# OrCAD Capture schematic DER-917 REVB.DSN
size Custom
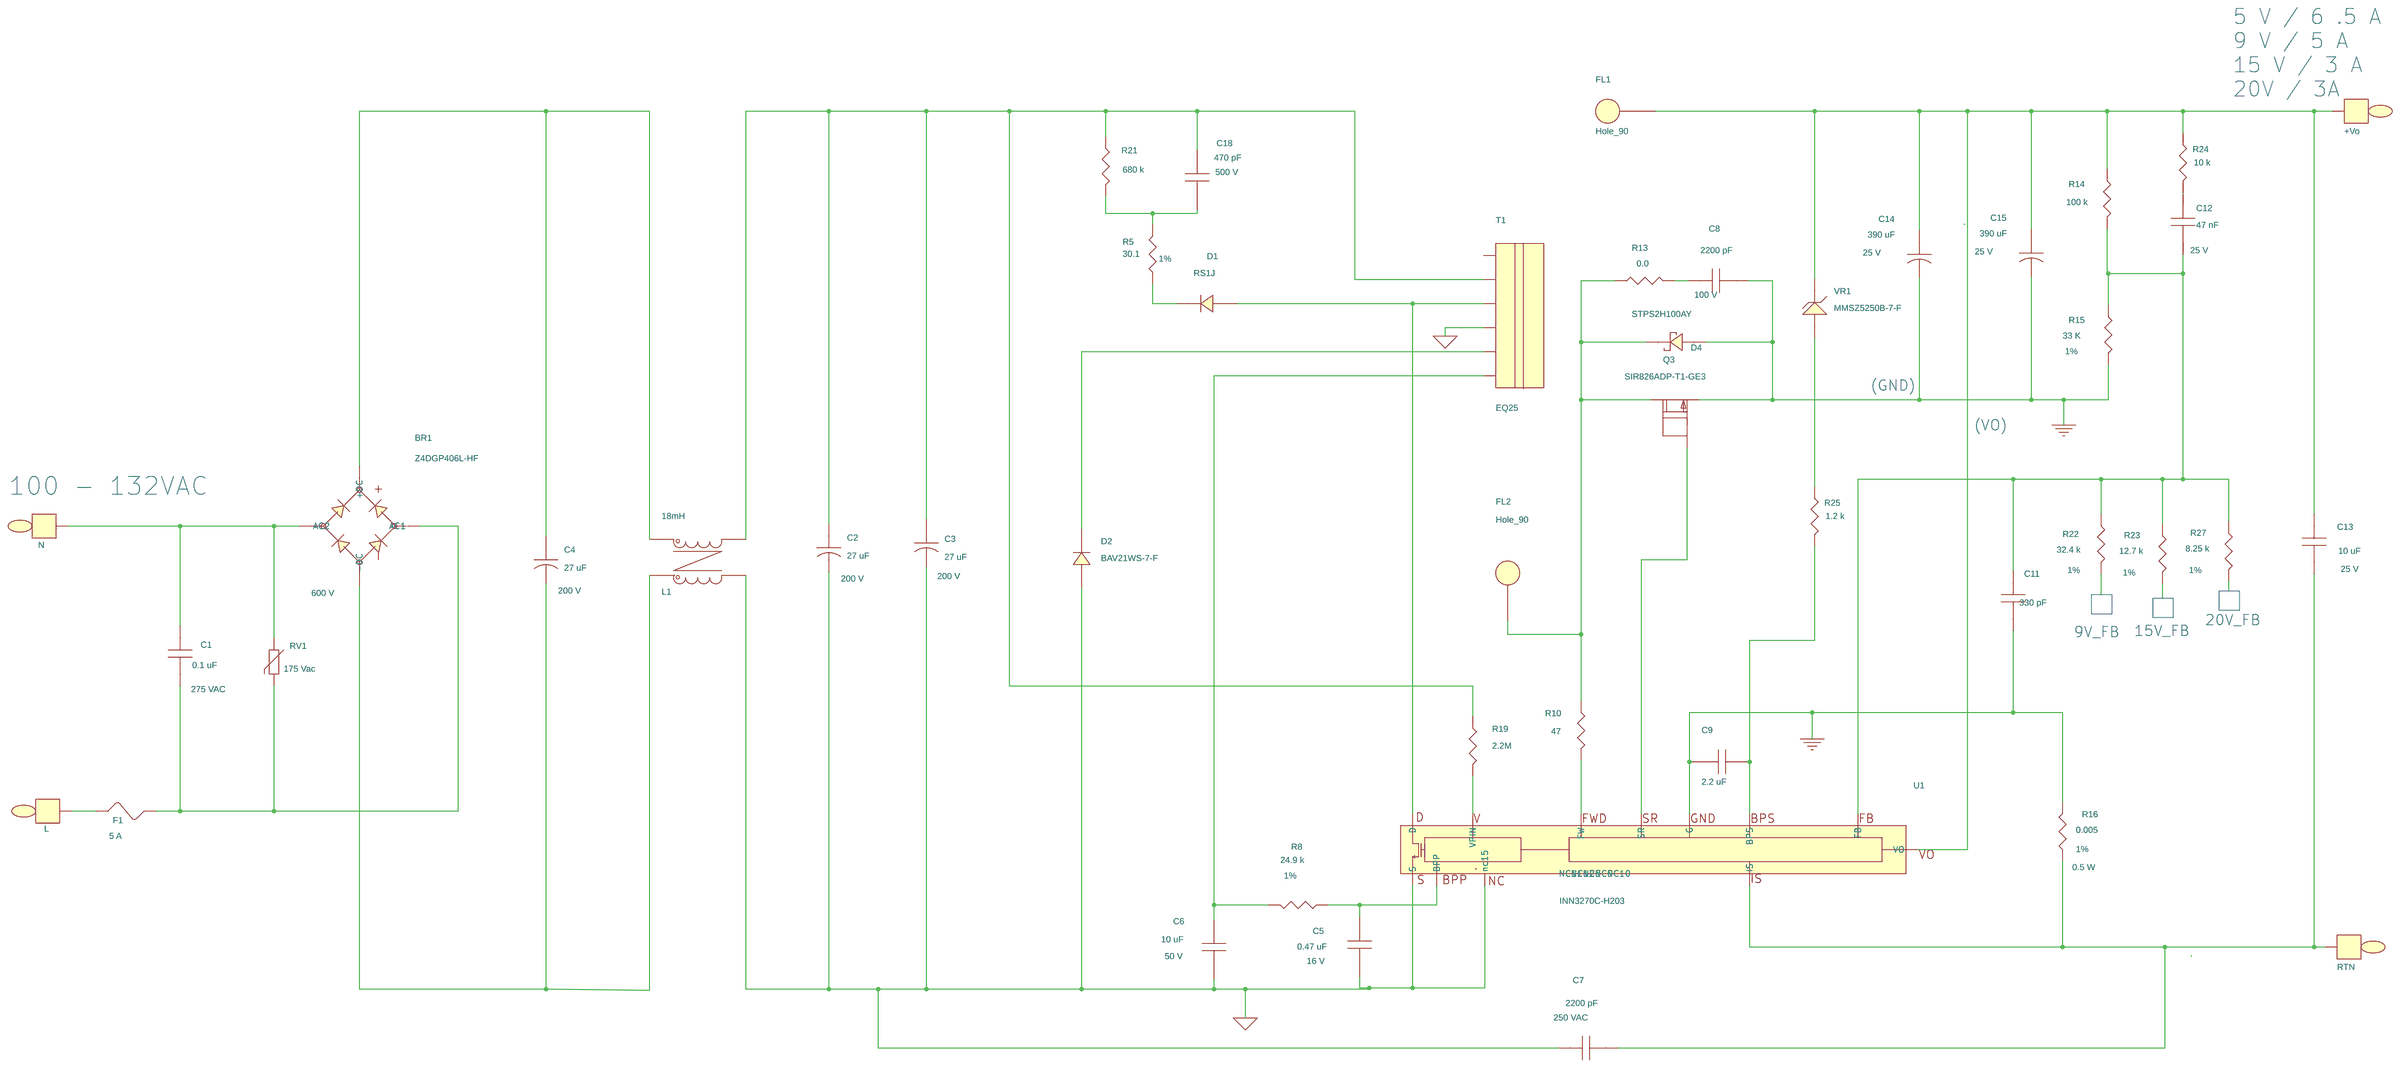
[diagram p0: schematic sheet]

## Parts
BR1  Z4DGP406L-HF  [pi_sm_d_z4d]
C1  0.1 uF  [pinpxcaprad5x13x11p1mm040]
C2  27 uF  [pipolcapcyld400ls200040]
C3  27 uF  [pipolcapcyld400ls200040]
C4  27 uF  [pipolcapcyld400ls200040]
C5  0.47 uF  [pismc0603]
C6  10 uF  [pismc1206]
C7  2200 pF  [pinpcaprad9p0D10p0LS030]
C8  2200 pF  [pismc0603]
C9  2.2 uF  [pismc0603]
C11  330 pF  [pismc0603]
C12  47 nF  [pismc0603]
C13  10 uF  [pismc1206]
C14  390 uF  [pipolcapcyld400ls200040]
C15  390 uF  [pipolcapcyld400ls200040]
C18  470 pF  [pismc0805]
D1  RS1J  [pismdsma]
D2  BAV21WS-7-F  [pismsod323]
D4  STPS2H100AY  [pismdsma]
F1  5 A  [pi_rst_microfuse]
FL1  Hole_90  [pi_hole_70mil]
FL2  Hole_90  [pi_hole_70mil]
L1  18mH  [pi_CMC_18mH_Sumida]
Q3  SIR826ADP-T1-GE3  [pismpqfn5x6b]
R5  30.1  [pismr0805]
R8  24.9 k  [pismr0603]
R10  47  [pismr0603]
R13  0.0  [pismr1206]
R14  100 k  [pismr0603]
R15  33 K  [pismr0603]
R16  0.005  [pismr0805]
R19  2.2M  [pismr1206]
R21  680 k  [pismr0805]
R22  32.4 k  [pismr0603]
R23  12.7 k  [pismr0603]
R24  10 k  [pismr0603]
R25  1.2 k  [pismr0603]
R27  8.25 k  [pismr0603]
RV1  175 Vac  [pi_disc_335x240ls200d040]
T1  EQ25  [pi_bobbin_eq-25_6p]
TP1  N  [pitpkeystone100x100]
TP2  L  [pitpkeystone100x100]
TP10  RTN  [pitpkeystone100x100]
TP11  +Vo  [pitpkeystone100x100]
U1  INN3270C-H203  [pi_ic_insop_24d]
VR1  MMSZ5250B-7-F  [pi_sm_sod-123_12]

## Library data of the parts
BR1 = DISCRETE_BRIDGE_+~~-: Disp_Voltage: 600 V; Part Number: 15-01613-00
C1 = CAP_NP: ALT_SYMBOLS: pinpxcaprad5x13x11p1mm040h; COMPGROUP: 1; Disp_Voltage: 275 VAC; FPLIST: pinpxcaprad5x13x11p1mm040,pinpxcaprad5x13x11p1mm040h; Part Number: 20-01410-00; Voltage: 275 VAC
C2-C4 = CAP_POL: ALT_SYMBOLS: pipolcapclyd400x675ls200040h; Disp_Voltage: 200 V; FPLIST: pipolcapcyld400ls200040,pipolcapclyd400x675ls200040h; Part Number: 20-00610-00; Voltage: 200 V
C5 = CAP_NP: Disp_Voltage: 16 V; Part Number: 20-08990-00; Voltage: 16 V
C6 = CAP_NP: ALT_SYMBOLS: pismc1206_1; Disp_Voltage: 50 V; FPLIST: pismc1206,pismc1206_1; Part Number: 20-08995-00; Voltage: 50 V
C7 = CAP_NP: COMPGROUP: 3; Disp_Voltage: 250 VAC; PCB Editor PCBFP: pinpycaprad540x290ls400040; Part Number: 20-09158-00; Voltage: 250 VAC
C8 = CAP_NP: Disp_Voltage: 100 V; Part Number: 20-01411-00; Voltage: 100 V
C9 = CAP_NP: Disp_Voltage: 10 V; Part Number: 20-08740-00; Voltage: 10V
C11 = CAP_NP: Disp_Voltage: 50 V; Part Number: 20-08676-00; Voltage: 50 V
C12 = CAP_NP: Disp_Voltage: 25 V; Part Number: 20-08756-00; Voltage: 25 V
C13 = CAP_NP: Disp_Voltage: 25 V; Part Number: 20-08608-00; Voltage: 25 V
C14 C15 = CAP_POL: ALT_SYMBOLS: pipolcapclyd400x530ls200030h; COMPGROUP: 3; Disp_Voltage: 25 V; FPLIST: pipolcapcyld400ls200040,pipolcapclyd400x530ls200030h; Part Number: 20-08908-00; Voltage: 25 V
C18 = CAP_NP: Disp_Voltage: 500 V; Part Number: 20-09175-00; Voltage: 500 V
D1 = DIODE: Part Number: 15-00432-00
D2 = DIODE: COMPGROUP: 1; Part Number: 15-00385-00
D4 = DIODE_SCHOTTKY: Disp_Voltage: 100 V; Part Number: 15-00985-00
F1 = FUSE: ALT_SYMBOLS: pirstmicrofusehoz; FPLIST: pi_rst_microfuse,pirstmicrofusehoz; Part Number: 40-00052-00
FL1 FL2 = FlyingLead: Part Number: 35-00282-00
L1 = TORRID_4P_12_43a: ALT_SYMBOLS: pi_CMC_18mH_SumidaW,pi_CMC_18mH_Sumida_H; FPLIST: pi_CMC_18mH_Sumida,pi_CMC_18mH_SumidaW,pi_CMC_18mH_Sumida_H; Part Number: 30-00462-00
Q3 = FET_N_SGD_123_4_5678: Part Number: 50-00154-00
R5 = R: Disp_Tol: 1%; Part Number: 05-00538-00
R8 = R: Disp_Tol: 1%; Part Number: 05-03222-00
R10 = R: Part Number: 05-01656-00
R13 = R: Part Number: 05-03160-00
R14 = R: Disp_Tol: 1%; Part Number: 05-01174-00
R15 = R: Disp_Tol: 1%; Part Number: 05-06465-00
R16 = R: Disp_Power: 0.5 W; Disp_Tol: 1%; Part Number: 05-06481-00
R19 = R: Part Number: 05-01429-00
R21 = R: Part Number: 05-01587-00
R22 = R: Disp_Tol: 1%; Part Number: 05-03233-00
R23 = R: Disp_Tol: 1%; Part Number: 05-03192-00
R24 = R: Part Number: 05-01712-00
R25 = R: Part Number: 05-01690-00
R27 = R: Disp_Tol: 1%; Part Number: 05-01166-00
RV1 = VARISTOR: Part Number: 85-00025-00
T1 = BEQ25_6P: Part Number: 25-01136-00
TP1 TP10 = TESTPOINT: Part Number: 35-00079-00
TP2 = TESTPOINT: Part Number: 35-00081-00
TP11 = TESTPOINT: Part Number: 35-00080-00
U1 = Inno3CP_P15: Part Number: 10-01044-06
VR1 = DIODE_ZENER: Part Number: 15-01093-00

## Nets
GND_POWER: C8.2 C9.2 C11.2 C14.2 C15.2 D4.2 Q3.1(S) R15.2 R16.1 U1.2(G)
GND_SIGNAL: C2.2 C3.2 C5.2 C6.2 C7.1 D2.2 L1.3 T1.4 U1.15(nc15) U1.16(S)
NC8: U1.8(NC8)
NC9: U1.9(NC9)
NC10: U1.10(NC10)
NC11: U1.11(NC11)
NC12: U1.12(NC12)
N11018979: C13.1 C14.1 C15.1 FL1.1 R14.1 R24.1 TP11.1 U1.6(VO) VR1.1
N11018991: C7.2 C13.2 R16.2 TP10.1 U1.1(IS)
N11019023: R10.2 U1.7(FW)
N11019027: D4.1 FL2.1 Q3.5(D) R10.1 R13.1
N11019153: D1.1 R5.2
N11019263: BR1.4(-DC) C4.2 L1.4
N11019293: C5.1 R8.2 U1.14(BPP)
N11019397: BR1.3(AC2) C1.1 RV1.1 TP1.1
N11019401: C8.1 R13.2
N11019613: C2.1 C3.1 C18.1 L1.2 R19.2 R21.1 T1.2
N11019673: BR1.2(AC1) C1.2 F1.2 RV1.2
N11019681: BR1.1(+DC) C4.1 L1.1
N11019743: C11.1 C12.2 R14.2 R15.1 R22.1 R23.1 R27.1 U1.3(FB)
N11020702: C18.2 R5.1 R21.2
N11020753: D1.2 T1.3 U1.24(D)
N11026403: F1.1 TP2.1
N11111738: C12.1 R24.2
N11114484: R25.1 VR1.2
N12705759: D2.1 T1.5
N12705920: C6.1 R8.1 T1.6
N12717194: R19.1 U1.13(VPIN)
N12724298: Q3.4(G) U1.5(SR)
N12728725: C9.1 R25.2 U1.4(BPS)

Not connected (* = marked no-connect by the designer): Q3 2(S2) 3(S3) 6(D6) 7(D7) 8(D8); R22 2; R23 2; R27 2; T1 1

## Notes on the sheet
- 5 V / 6 .5 A
  9 V / 5 A
  15 V / 3 A
  20V / 3A
- (GND)
- (VO)
- 100 - 132VAC
- 20V_FB
- 9V_FB
- 15V_FB
